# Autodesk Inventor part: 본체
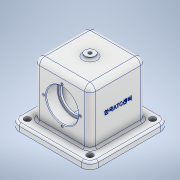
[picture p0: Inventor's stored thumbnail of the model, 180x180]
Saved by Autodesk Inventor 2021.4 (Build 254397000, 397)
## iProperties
Created: 2022-07
Part Number: 본체
Material: 알루미늄 6061
Document SubType Name: Modeling
Designer: j
Density: 2.7 g/cm^3
Appearance: 알루미늄 - 평지
Author: j
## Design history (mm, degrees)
sketch "스케치1"
  geometry: L1 (-41, -48)-(41, -48); L2 (41, -48)-(41, 42); L3 (41, 42)-(-41, 42); L4 (-41, 42)-(-41, -48); 1 further point
  constraints: 8 end point, 2 parallel, 1 horizontal, 1 perpendicular
  dimensions: "d0" = 82 distance of L2.end L3.end; "d1" = 90 distance of L1.end L2.end; "d2" = 48 distance from line of L1 point (0, 0); "d3" = 41 distance from line of L2 point (0, 0) (= 0.5 x d0)
extrude "돌출1" new body sketch "스케치1" stored distance "d4" = 82; taper "d5" = 0 deg
sketch "스케치2"
  geometry: L1 (-17, 17)-(99, 17); L2 (99, 17)-(99, -99); L3 (99, -99)-(-17, -99); L4 (-17, -99)-(-17, 17); L5 (-17, 17)-(99, -99); L6 (99, 17)-(-17, -99); 1 further point
  constraints: 12 end point, 2 midpoint, 2 parallel, 1 horizontal, 1 perpendicular
  dimensions: "d6" = 116 distance of L2.end L3.end; "d7" = 116 distance of L1.end L2.end
extrude "돌출2" join sketch "스케치2" distance "d8" = 10; taper "d9" = 0 deg
sketch "스케치3"
  geometry: C1 r 7.5 at (41, 41); 1 further point
  constraints: 1 centre point, 1 coincident
  dimensions: "d10" = 15 diameter of C1
extrude "돌출3" join sketch "스케치3" distance "d11" = 4; taper "d12" = 0 deg
sketch "스케치4"
  geometry: L1 (23.5, 41)-(-23.5, 41); L2 (-23.5, 41)-(-23.5, -41); L3 (-23.5, -41)-(23.5, -41); L4 (23.5, -41)-(23.5, 41); L5 (23.5, 41)-(-23.5, -41); L6 (-23.5, 41)-(23.5, -41); L7 (42, -41)-(-38, -41) reference; L8 (-23.5, 24)-(23.5, 24); L9 (23.5, 24)-(23.5, -24); L10 (23.5, -24)-(-23.5, -24); L11 (-23.5, -24)-(-23.5, 24); L12 (-23.5, 24)-(23.5, -24); L13 (23.5, 24)-(-23.5, -24); L14 (-20, 24)-(20, 24); L15 (20, 24)-(20, -24); L16 (20, -24)-(-20, -24); L17 (-20, -24)-(-20, 24); L18 (-20, 24)-(20, -24); L19 (20, 24)-(-20, -24); L20 (0, -81.2)-(0, 81.2) reference; 7 further points
  constraints: 36 end point, 8 midpoint, 6 parallel, 3 horizontal, 3 perpendicular, 2 point on line
  dimensions: "d13" = 47 distance between parallel lines of L2 L4; "d14" = 17 distance between parallel lines of L3 L10; "d15" = 40 distance between parallel lines of L17 L15
revolve "회전1" sketch "스케치4" stored, may be unused: angle "d16" = 90 deg
sketch "스케치5"
  geometry: L1 (28, 79)-(88, 79); L2 (88, 79)-(88, 37); L3 (88, 37)-(28, 37); L4 (28, 37)-(28, 79); L5 (28, 79)-(88, 37); L6 (88, 79)-(28, 37); 1 further point
  constraints: 12 end point, 2 midpoint, 2 parallel, 1 horizontal, 1 perpendicular
  dimensions: "d17" = 60 distance of L2.end L3.end; "d18" = 42 distance of L1.end L2.end
extrude "돌출4" cut sketch "스케치5" distance "d19" = 80; taper "d20" = 0 deg
fillet "모깎기1" dims "d21" = 0.6, "d22" = 3, "d23" = 8, "d24" = 12
chamfer "모따기1" distance "d25" = 1; stored, may be unused: second distance "d26" = 2, angle "d27" = 45 deg
sketch "스케치6"
  geometry: 2 further points
  constraints: 1 coincident
hole "구멍1" sketch "스케치6" at (0, 0) diameter "d28" = 4.917; stored, may be unused: countersink angle "d32" = 90 deg, drill point angle "d34" = 118 deg; dims "d29" = 20, "d30" = 4, "d31" = 2, "d33" = 17.1
sketch "스케치7"
  geometry: L1 (87, 99)-(-5, 99) reference; L2 (-17, 87)-(-17, -5) reference; C1 r 4.5 at (-5, 87); 1 further point
  constraints: 1 centre point
  dimensions: "d35" = 9 diameter of C1; "d36" = 12 distance from line of L1 C1.centre; "d37" = 12 distance from line of L2 C1.centre
extrude "돌출5" cut sketch "스케치7" extent not by distance; stored distance "d38" = 0; taper "d39" = 0 deg
sketch "스케치8"
  geometry: L1 (0, 0)-(0, 27); L2 (-27, 32)-(27, 32) reference; L3 (0, 0)-(27, 0); 1 further point
  constraints: 4 end point, 2 perpendicular, 1 coincident, 1 horizontal
  dimensions: "d46" = 27 distance of L1.start L1.end; "d47" = 90 deg angle of L3 L1 (derived)
hole "구멍2" sketch "스케치8" at (0, 27) diameter "d48" = 3.242; stored, may be unused: countersink angle "d52" = 90 deg, drill point angle "d54" = 118 deg; dims "d49" = 8, "d50" = 4, "d51" = 2, "d53" = 10
sketch "스케치9"
  geometry: L1 (0, 0)-(0, 27); L2 (7.5, 46)-(-7.5, 46) reference; C1 r 1.621 at (0, 27) reference; 1 further point
  constraints: 2 end point, 1 coincident, 1 perpendicular
  dimensions: "d55" = 27 distance of L1.start L1.end
hole "구멍3" sketch "스케치9" at (0, 27) diameter "d56" = 3.242; stored, may be unused: countersink angle "d60" = 90 deg, drill point angle "d62" = 118 deg; dims "d57" = 8, "d58" = 4, "d59" = 2, "d61" = 10
sketch "스케치10"
  geometry: L1 (79, -13)-(-13, -13) reference; L2 (33, -31.8)-(33, 99.8) reference; 2 further points
  constraints: 1 point on line, 1 other
  dimensions: "d66" = 48 distance from line of L1 point (33, 35)
feature "엠보싱1" sketch "스케치10" dims "d1" = 90, "d67" = 0.5, "d68" = 0
node "솔리드1"
pattern_linear "직사각형 패턴1" dims "d42" = 92, "d45" = 92
pattern_circular "원형 패턴1" dims angle "d64" = 360 deg
feature "A9D066F2-1C7D-4E18-AEED-F7BC21143FA4" dims "d28" = 4.917, "d29" = 20, "d30" = 4, "d31" = 2, "d32" = 90 deg, "d33" = 17.1, "d34" = 118 deg
